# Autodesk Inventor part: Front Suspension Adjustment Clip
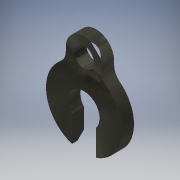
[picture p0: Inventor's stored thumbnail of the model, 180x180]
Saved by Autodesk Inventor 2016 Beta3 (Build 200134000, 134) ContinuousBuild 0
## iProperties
Shininess: 41.0
Compacted: True
Length Units: 11272
Angle Units: 11279
Time Units: 11290
Mass Units: 11286
Length Display Precision: 3
Angle Display Precision: 2
Company: Autodesk
Created: 2001-02
Part Number: Front Suspension Adjustment Clip
Document SubType Name: Modeling
Designer: Autodesk, Inc.
Project: Inventor Samples
Density: 1.13 g/cm^3
Material: Nylon-6/6
Mass: 0.0594254 g
Surface Area: 1.41637 cm^2
Volume: 0.0525888 cm^3
Appearance: Gunmetal
Density: 0.0
Volumn: 0.0
Area: 0.0
PropertySet Name: Model Information
Control State: 0
Master: False
Checked Out: False
Author: Autodesk, Inc.
Revision Number: A
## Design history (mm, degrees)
sketch "Sketch1"
  geometry: L1 (1.937, 15.448)-(1.937, 16.693); L2 (5.747, 16.693)-(5.747, 15.448); L3 (2.572, 10.876)-(2.572, 8.137); L4 (5.112, 10.876)-(5.112, 8.137); C1 r 1.048 at (3.842, 16.693); A1 r 1.651 centre (3.842, 11.931) between (5.112, 10.876) and (2.572, 10.876); A2 r 1.905 centre (3.842, 16.693) between (5.747, 16.693) and (1.937, 16.693); A3 r 4.001 centre (3.842, 11.931) between (1.937, 15.448) and (2.572, 8.137); A4 r 4.001 centre (3.842, 11.931) between (5.112, 8.137) and (5.747, 15.448)
  constraints: 8 end point, 8 point on circle, 5 centre point, 4 parallel, 2 coincident, 2 tangent, 1 concentric, 1 vertical, 1 other
  dimensions: "d1" = 3.302 diameter of A1; "d2" = 1.905 radius of A2; "d3" = 2.0955 diameter of C1; "d4" = 4.7625 distance of A3.centre A2.centre; "d5" = 2.54 distance between parallel lines of L4 L3; "d6" = 1.27 distance from line of A3.centre L3 (= 0.5 x d5); "d7" = 4.0005 radius of A4
extrude "Extrusion1" new body sketch "Sketch1" distance "d8" = 1.27; taper "d9" = 0 deg
fillet "Fillet1" dims "d10" = 1.5875
body "Solid1"
other parameters: "d0" = 4.0005
